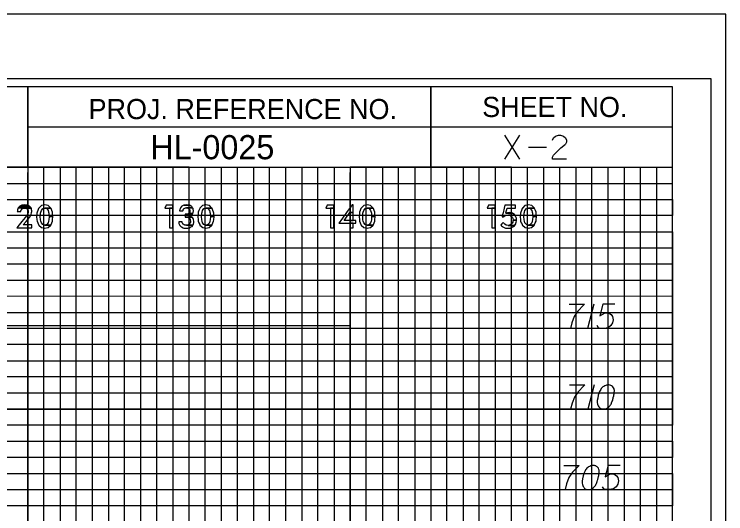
# Model space of a CAD drawing. Extents: x -13 to 323, y -5 to 1431.
# Drawn here: x 279.16 to 323.3, y 183.5 to 214.5 of the extents above; entities that cross this region are included whole.
import ezdxf

# ---------------------------------------------------------------- set-up
doc = ezdxf.new("R2010")
doc.units = 0
for name, color, linetype in [('Prop XS Elevation Labels', 7, 'Continuous'), ('Prop XS Offset Labels', 7, 'Continuous'), ('Prop XS Project Number', 7, 'Continuous'), ('Prop XS Sheet Number', 7, 'Continuous'), ('Scratch_Level_3', 7, 'Continuous'), ('Sheet Cross Section CELL', 7, 'Continuous'), ('Sheet Cross Section Grid Major CELL', 7, 'Continuous'), ('Sheet Cross Section Grid Middle CELL', 7, 'Continuous'), ('Sheet Cross Section Grid Minor 1 CELL', 7, 'Continuous'), ('Sheet Cross Section Grid Minor 2 CELL', 7, 'Continuous'), ('Sheet Cutting Line CELL', 7, 'Continuous'), ('Sheet DOT Grid CELL', 7, 'Continuous'), ('Sheet Plot Border Inside CELL', 7, 'Continuous'), ('Sheet Plot Border Outside CELL', 7, 'Continuous')]:
    doc.layers.add(name, color=color, linetype=linetype)

msp = doc.modelspace()

# ---------------------------------------------------------------- linework, layer by layer
at = {"layer": 'Prop XS Elevation Labels'}
for p, q in [((315.124, 196.5), (314.723, 195)), ((315.142, 191.5), (314.74, 190))]:
    msp.add_line(p, q, dxfattribs=at)
for points in [[(313.589, 196.5), (314.533, 196.5), (314.474, 196.441), (314.132, 196.075), (313.896, 195.744), (313.754, 195.354), (313.659, 195)], [(316.411, 196.5), (315.667, 196.5), (315.478, 195.791), (315.821, 195.969), (316.022, 195.969), (316.187, 195.862), (316.282, 195.744), (316.305, 195.543), (316.27, 195.342), (316.175, 195.177), (316.01, 195.047), (315.726, 195), (315.514, 195), (315.408, 195.047), (315.313, 195.177)], [(313.606, 191.5), (314.551, 191.5), (314.492, 191.441), (314.149, 191.075), (313.913, 190.744), (313.772, 190.354), (313.677, 190)], [(316.039, 191.5), (316.016, 191.5), (315.945, 191.488), (315.898, 191.476), (315.862, 191.465), (315.803, 191.441), (315.732, 191.406), (315.673, 191.37), (315.614, 191.323), (315.579, 191.276), (315.543, 191.217), (315.508, 191.158), (315.472, 191.087), (315.449, 191.039), (315.425, 190.969), (315.39, 190.85), (315.354, 190.673), (315.331, 190.531), (315.331, 190.402), (315.343, 190.307), (315.39, 190.201), (315.425, 190.142), (315.484, 190.071), (315.555, 190.024), (315.591, 190.012), (315.661, 190), (315.72, 190), (315.815, 190.012), (315.898, 190.035), (315.957, 190.071), (316.039, 190.13), (316.075, 190.165), (316.122, 190.213), (316.157, 190.26), (316.181, 190.295), (316.205, 190.354), (316.217, 190.378), (316.24, 190.437), (316.264, 190.508), (316.287, 190.579), (316.299, 190.626), (316.311, 190.661), (316.323, 190.709), (316.347, 190.815), (316.358, 190.874), (316.37, 190.933), (316.382, 191.016), (316.394, 191.122), (316.394, 191.158), (316.382, 191.205), (316.37, 191.252), (316.335, 191.323), (316.299, 191.37), (316.264, 191.406), (316.217, 191.441), (316.169, 191.465), (316.134, 191.476), (316.098, 191.488), (316.039, 191.5)], [(313.258, 186.5), (314.203, 186.5), (314.144, 186.441), (313.801, 186.075), (313.565, 185.744), (313.423, 185.354), (313.329, 185)], [(315.1, 186.5), (315.077, 186.5), (315.006, 186.488), (314.959, 186.476), (314.923, 186.465), (314.864, 186.441), (314.793, 186.406), (314.734, 186.37), (314.675, 186.323), (314.64, 186.276), (314.604, 186.217), (314.569, 186.158), (314.534, 186.087), (314.51, 186.039), (314.486, 185.969), (314.451, 185.85), (314.415, 185.673), (314.392, 185.531), (314.392, 185.402), (314.404, 185.307), (314.451, 185.201), (314.486, 185.142), (314.545, 185.071), (314.616, 185.024), (314.652, 185.012), (314.723, 185), (314.781, 185), (314.876, 185.012), (314.959, 185.035), (315.018, 185.071), (315.1, 185.13), (315.136, 185.165), (315.183, 185.213), (315.219, 185.26), (315.242, 185.295), (315.266, 185.354), (315.278, 185.378), (315.301, 185.437), (315.325, 185.508), (315.349, 185.579), (315.36, 185.626), (315.372, 185.661), (315.384, 185.709), (315.408, 185.815), (315.419, 185.874), (315.431, 185.933), (315.443, 186.016), (315.455, 186.122), (315.455, 186.158), (315.443, 186.205), (315.431, 186.252), (315.396, 186.323), (315.36, 186.37), (315.325, 186.406), (315.278, 186.441), (315.23, 186.465), (315.195, 186.476), (315.16, 186.488), (315.1, 186.5)], [(316.742, 186.5), (315.998, 186.5), (315.809, 185.791), (316.152, 185.969), (316.352, 185.969), (316.518, 185.862), (316.612, 185.744), (316.636, 185.543), (316.6, 185.342), (316.506, 185.177), (316.341, 185.047), (316.057, 185), (315.845, 185), (315.738, 185.047), (315.644, 185.177)]]:
    msp.add_lwpolyline(points, dxfattribs=at)
at = {"layer": 'Prop XS Offset Labels'}
for points in [[(279.512, 202.585), (279.507, 202.583), (280.108, 202.583), (280.106, 202.585), (279.974, 202.645), (279.958, 202.652), (279.794, 202.668), (279.794, 202.668), (279.685, 202.652), (279.637, 202.645)], [(280.851, 201.255), (281.051, 201.214), (281.245, 201.255), (281.256, 201.257), (281.422, 201.409), (281.048, 201.409), (281.038, 201.411), (281.033, 201.413), (280.928, 201.442), (280.841, 201.555), (280.841, 201.556), (280.841, 201.556), (280.813, 201.657), (280.813, 201.659), (280.793, 201.732), (280.792, 201.736), (280.774, 201.939), (280.774, 201.941), (280.774, 201.943), (280.792, 202.145), (280.812, 202.222), (280.813, 202.224), (280.839, 202.322), (280.84, 202.325), (280.928, 202.44), (281.041, 202.469), (281.045, 202.47), (281.055, 202.473), (281.425, 202.473), (281.262, 202.622), (281.254, 202.624), (281.053, 202.668), (281.053, 202.668), (280.845, 202.624), (280.843, 202.622), (280.681, 202.473), (280.678, 202.47), (280.678, 202.469), (280.665, 202.44), (280.618, 202.325), (280.617, 202.322), (280.577, 202.224), (280.576, 202.222), (280.568, 202.145), (280.547, 201.943), (280.547, 201.941), (280.547, 201.939), (280.567, 201.736), (280.567, 201.732), (280.575, 201.659), (280.575, 201.657), (280.616, 201.556), (280.617, 201.555), (280.663, 201.442), (280.675, 201.413), (280.676, 201.411), (280.679, 201.409), (280.848, 201.257)], [(288.581, 202.641), (288.492, 202.459), (288.99, 202.459), (288.99, 202.641)], [(289.42, 202.315), (289.418, 202.297), (289.626, 202.297), (289.627, 202.315), (289.639, 202.365), (289.64, 202.372), (289.641, 202.373), (289.683, 202.433), (289.688, 202.436), (289.696, 202.44), (289.748, 202.47), (289.785, 202.476), (289.795, 202.478), (289.835, 202.485), (290.217, 202.485), (290.165, 202.561), (290.129, 202.582), (290.128, 202.582), (290.022, 202.644), (289.982, 202.65), (289.69, 202.65), (289.678, 202.644), (289.553, 202.582), (289.536, 202.561), (289.471, 202.485), (289.466, 202.478), (289.465, 202.476), (289.463, 202.47), (289.452, 202.44), (289.45, 202.436), (289.449, 202.433), (289.428, 202.373), (289.427, 202.372), (289.425, 202.365)], [(289.853, 202.668), (289.69, 202.65), (289.982, 202.65)], [(290.851, 201.255), (291.051, 201.214), (291.245, 201.255), (291.256, 201.257), (291.422, 201.409), (291.048, 201.409), (291.038, 201.411), (291.033, 201.413), (290.928, 201.442), (290.841, 201.555), (290.841, 201.556), (290.841, 201.556), (290.813, 201.657), (290.813, 201.659), (290.793, 201.732), (290.792, 201.736), (290.774, 201.939), (290.774, 201.941), (290.774, 201.943), (290.792, 202.145), (290.812, 202.222), (290.813, 202.224), (290.839, 202.322), (290.84, 202.325), (290.928, 202.44), (291.041, 202.469), (291.045, 202.47), (291.055, 202.473), (291.425, 202.473), (291.262, 202.622), (291.254, 202.624), (291.053, 202.668), (291.053, 202.668), (290.845, 202.624), (290.843, 202.622), (290.681, 202.473), (290.678, 202.47), (290.678, 202.469), (290.665, 202.44), (290.618, 202.325), (290.617, 202.322), (290.577, 202.224), (290.576, 202.222), (290.568, 202.145), (290.547, 201.943), (290.547, 201.941), (290.547, 201.939), (290.567, 201.736), (290.567, 201.732), (290.575, 201.659), (290.575, 201.657), (290.616, 201.556), (290.617, 201.555), (290.663, 201.442), (290.675, 201.413), (290.676, 201.411), (290.679, 201.409), (290.848, 201.257)], [(298.581, 202.641), (298.492, 202.459), (298.99, 202.459), (298.99, 202.641)], [(299.411, 201.693), (299.297, 201.534), (300.35, 201.534), (300.35, 201.693), (299.618, 201.693), (299.878, 202.059), (299.935, 202.139), (299.977, 202.199), (300.179, 202.199), (300.179, 202.668), (300.114, 202.668), (299.775, 202.199), (299.733, 202.139), (299.675, 202.059)], [(300.851, 201.255), (301.051, 201.214), (301.245, 201.255), (301.256, 201.257), (301.422, 201.409), (301.048, 201.409), (301.038, 201.411), (301.033, 201.413), (300.928, 201.442), (300.841, 201.555), (300.841, 201.556), (300.841, 201.556), (300.813, 201.657), (300.813, 201.659), (300.793, 201.732), (300.792, 201.736), (300.774, 201.939), (300.774, 201.941), (300.774, 201.943), (300.792, 202.145), (300.812, 202.222), (300.813, 202.224), (300.839, 202.322), (300.84, 202.325), (300.928, 202.44), (301.041, 202.469), (301.045, 202.47), (301.055, 202.473), (301.425, 202.473), (301.262, 202.622), (301.254, 202.624), (301.053, 202.668), (301.053, 202.668), (300.845, 202.624), (300.843, 202.622), (300.681, 202.473), (300.678, 202.47), (300.678, 202.469), (300.665, 202.44), (300.618, 202.325), (300.617, 202.322), (300.577, 202.224), (300.576, 202.222), (300.568, 202.145), (300.547, 201.943), (300.547, 201.941), (300.547, 201.939), (300.567, 201.736), (300.567, 201.732), (300.575, 201.659), (300.575, 201.657), (300.616, 201.556), (300.617, 201.555), (300.663, 201.442), (300.675, 201.413), (300.676, 201.411), (300.679, 201.409), (300.848, 201.257)], [(308.581, 202.641), (308.492, 202.459), (308.99, 202.459), (308.99, 202.641)], [(309.427, 201.94), (309.424, 201.928), (309.495, 201.928), (309.508, 201.94), (309.524, 201.954), (309.595, 201.997), (309.627, 202.007), (309.697, 202.029), (309.811, 202.035), (310.219, 202.035), (310.211, 202.05), (310.076, 202.145), (309.655, 202.145), (309.658, 202.158), (309.658, 202.158), (309.663, 202.178), (309.738, 202.456), (310.263, 202.456), (310.263, 202.641), (309.6, 202.641), (309.554, 202.456), (309.486, 202.178), (309.481, 202.158), (309.478, 202.145), (309.454, 202.05), (309.451, 202.035), (309.449, 202.029), (309.444, 202.007), (309.441, 201.997), (309.431, 201.954)], [(310.851, 201.255), (311.051, 201.214), (311.245, 201.255), (311.256, 201.257), (311.422, 201.409), (311.048, 201.409), (311.038, 201.411), (311.033, 201.413), (310.928, 201.442), (310.841, 201.555), (310.841, 201.556), (310.841, 201.556), (310.813, 201.657), (310.813, 201.659), (310.793, 201.732), (310.792, 201.736), (310.774, 201.939), (310.774, 201.941), (310.774, 201.943), (310.792, 202.145), (310.812, 202.222), (310.813, 202.224), (310.839, 202.322), (310.84, 202.325), (310.928, 202.44), (311.041, 202.469), (311.045, 202.47), (311.055, 202.473), (311.425, 202.473), (311.262, 202.622), (311.254, 202.624), (311.053, 202.668), (311.053, 202.668), (310.845, 202.624), (310.843, 202.622), (310.681, 202.473), (310.678, 202.47), (310.678, 202.469), (310.665, 202.44), (310.618, 202.325), (310.617, 202.322), (310.577, 202.224), (310.576, 202.222), (310.568, 202.145), (310.547, 201.943), (310.547, 201.941), (310.547, 201.939), (310.567, 201.736), (310.567, 201.732), (310.575, 201.659), (310.575, 201.657), (310.616, 201.556), (310.617, 201.555), (310.663, 201.442), (310.675, 201.413), (310.676, 201.411), (310.679, 201.409), (310.848, 201.257)], [(279.465, 201.432), (279.313, 201.25), (280.253, 201.25), (280.253, 201.432), (279.719, 201.432), (279.898, 201.638), (280.095, 201.879), (280.097, 201.881), (280.208, 202.069), (280.208, 202.069), (280.211, 202.074), (280.235, 202.193), (280.247, 202.254), (280.252, 202.279), (280.25, 202.29), (280.249, 202.293), (280.236, 202.354), (280.235, 202.36), (280.233, 202.37), (280.222, 202.421), (280.222, 202.421), (280.219, 202.435), (280.213, 202.461), (280.211, 202.464), (280.207, 202.468), (279.839, 202.468), (279.85, 202.464), (279.858, 202.461), (279.933, 202.435), (279.946, 202.421), (279.996, 202.37), (280, 202.36), (280.002, 202.354), (280.022, 202.293), (280.022, 202.29), (280.022, 202.279), (280.022, 202.254), (280.021, 202.193), (279.973, 202.074), (279.972, 202.069), (279.839, 201.881), (279.838, 201.879), (279.637, 201.638)], [(279.349, 202.279), (279.347, 202.254), (279.567, 202.254), (279.569, 202.279), (279.57, 202.29), (279.571, 202.293), (279.593, 202.354), (279.598, 202.36), (279.606, 202.37), (279.645, 202.421), (279.673, 202.435), (279.725, 202.461), (279.73, 202.464), (279.839, 202.468), (280.207, 202.468), (280.197, 202.479), (279.41, 202.479), (279.405, 202.468), (279.403, 202.464), (279.402, 202.461), (279.39, 202.435), (279.384, 202.421), (279.361, 202.37), (279.357, 202.36), (279.356, 202.354), (279.35, 202.293), (279.35, 202.29)], [(279.507, 202.583), (279.41, 202.479), (280.197, 202.479), (280.108, 202.583)], [(281.312, 202.145), (281.328, 201.943), (281.555, 201.943), (281.536, 202.145), (281.528, 202.222), (281.528, 202.224), (281.527, 202.224), (281.488, 202.322), (281.488, 202.322), (281.487, 202.325), (281.441, 202.44), (281.44, 202.44), (281.429, 202.469), (281.428, 202.47), (281.425, 202.473), (281.055, 202.473), (281.065, 202.47), (281.068, 202.469), (281.175, 202.44), (281.262, 202.325), (281.265, 202.322), (281.291, 202.224), (281.291, 202.222)], [(288.781, 202.459), (288.781, 201.25), (288.99, 201.25), (288.99, 202.459)], [(290.007, 202.155), (289.988, 202.131), (290.23, 202.131), (290.246, 202.155), (290.254, 202.201), (290.271, 202.289), (290.272, 202.295), (290.272, 202.297), (290.269, 202.315), (290.26, 202.365), (290.259, 202.372), (290.259, 202.373), (290.259, 202.373), (290.249, 202.433), (290.248, 202.436), (290.248, 202.44), (290.227, 202.47), (290.223, 202.476), (290.222, 202.478), (290.217, 202.485), (289.835, 202.485), (289.901, 202.478), (289.919, 202.476), (289.931, 202.47), (289.986, 202.44), (289.995, 202.436), (289.997, 202.433), (290.04, 202.373), (290.04, 202.372), (290.042, 202.365), (290.051, 202.315), (290.054, 202.297), (290.055, 202.295), (290.056, 202.289), (290.041, 202.201)], [(291.312, 202.145), (291.328, 201.943), (291.555, 201.943), (291.536, 202.145), (291.528, 202.222), (291.528, 202.224), (291.527, 202.224), (291.488, 202.322), (291.488, 202.322), (291.487, 202.325), (291.441, 202.44), (291.44, 202.44), (291.429, 202.469), (291.428, 202.47), (291.425, 202.473), (291.055, 202.473), (291.065, 202.47), (291.068, 202.469), (291.175, 202.44), (291.262, 202.325), (291.265, 202.322), (291.291, 202.224), (291.291, 202.222)], [(298.781, 202.459), (298.781, 201.25), (298.99, 201.25), (298.99, 202.459)], [(299.97, 202.059), (299.97, 201.693), (300.179, 201.693), (300.179, 202.059), (300.179, 202.139), (300.179, 202.199), (299.977, 202.199), (299.973, 202.139)], [(301.312, 202.145), (301.328, 201.943), (301.555, 201.943), (301.536, 202.145), (301.528, 202.222), (301.528, 202.224), (301.527, 202.224), (301.488, 202.322), (301.488, 202.322), (301.487, 202.325), (301.441, 202.44), (301.44, 202.44), (301.429, 202.469), (301.428, 202.47), (301.425, 202.473), (301.055, 202.473), (301.065, 202.47), (301.068, 202.469), (301.175, 202.44), (301.262, 202.325), (301.265, 202.322), (301.291, 202.224), (301.291, 202.222)], [(308.781, 202.459), (308.781, 201.25), (308.99, 201.25), (308.99, 202.459)], [(309.692, 202.158), (309.655, 202.145), (310.076, 202.145), (310.058, 202.158), (309.961, 202.178), (309.75, 202.178)], [(309.888, 202.192), (309.75, 202.178), (309.96, 202.178), (309.888, 202.192)], [(311.312, 202.145), (311.328, 201.943), (311.555, 201.943), (311.536, 202.145), (311.528, 202.222), (311.528, 202.224), (311.527, 202.224), (311.488, 202.322), (311.488, 202.322), (311.487, 202.325), (311.441, 202.44), (311.44, 202.44), (311.429, 202.469), (311.428, 202.47), (311.425, 202.473), (311.055, 202.473), (311.065, 202.47), (311.068, 202.469), (311.175, 202.44), (311.262, 202.325), (311.265, 202.322), (311.291, 202.224), (311.291, 202.222)], [(281.058, 201.411), (281.048, 201.409), (281.422, 201.409), (281.425, 201.411), (281.426, 201.413), (281.438, 201.442), (281.485, 201.555), (281.485, 201.556), (281.527, 201.657), (281.528, 201.659), (281.535, 201.732), (281.535, 201.736), (281.555, 201.939), (281.556, 201.941), (281.555, 201.943), (281.328, 201.943), (281.328, 201.941), (281.328, 201.939), (281.312, 201.736), (281.312, 201.732), (281.292, 201.659), (281.291, 201.657), (281.264, 201.556), (281.263, 201.555), (281.175, 201.442), (281.063, 201.413)], [(289.765, 201.956), (289.765, 201.9), (290.194, 201.9), (290.119, 201.956), (290.029, 201.983), (290.095, 202), (290.181, 202.053), (290.2, 202.084), (290.201, 202.085), (290.207, 202.095), (289.915, 202.095), (289.83, 202.085), (289.765, 202.084), (289.765, 202.053), (289.765, 202), (289.765, 201.983)], [(289.925, 201.416), (289.849, 201.401), (290.229, 201.401), (290.239, 201.416), (290.243, 201.423), (290.243, 201.423), (290.275, 201.471), (290.277, 201.479), (290.277, 201.482), (290.283, 201.516), (290.292, 201.562), (290.293, 201.567), (290.303, 201.62), (290.297, 201.662), (290.285, 201.751), (290.283, 201.763), (290.25, 201.826), (290.223, 201.877), (290.222, 201.88), (290.197, 201.898), (290.194, 201.9), (289.81, 201.9), (289.877, 201.898), (289.951, 201.88), (289.963, 201.877), (290.033, 201.826), (290.07, 201.763), (290.077, 201.751), (290.092, 201.662), (290.088, 201.62), (290.082, 201.567), (290.08, 201.562), (290.057, 201.516), (290.039, 201.482), (290.035, 201.479), (290.025, 201.471), (289.957, 201.423)], [(289.988, 202.131), (289.915, 202.095), (290.207, 202.095), (290.23, 202.131)], [(291.058, 201.411), (291.048, 201.409), (291.422, 201.409), (291.425, 201.411), (291.426, 201.413), (291.438, 201.442), (291.485, 201.555), (291.485, 201.556), (291.527, 201.657), (291.528, 201.659), (291.535, 201.732), (291.535, 201.736), (291.555, 201.939), (291.556, 201.941), (291.555, 201.943), (291.328, 201.943), (291.328, 201.941), (291.328, 201.939), (291.312, 201.736), (291.312, 201.732), (291.292, 201.659), (291.291, 201.657), (291.264, 201.556), (291.263, 201.555), (291.175, 201.442), (291.063, 201.413)], [(301.058, 201.411), (301.048, 201.409), (301.422, 201.409), (301.425, 201.411), (301.426, 201.413), (301.438, 201.442), (301.485, 201.555), (301.485, 201.556), (301.527, 201.657), (301.528, 201.659), (301.535, 201.732), (301.535, 201.736), (301.555, 201.939), (301.556, 201.941), (301.555, 201.943), (301.328, 201.943), (301.328, 201.941), (301.328, 201.939), (301.312, 201.736), (301.312, 201.732), (301.292, 201.659), (301.291, 201.657), (301.264, 201.556), (301.263, 201.555), (301.175, 201.442), (301.063, 201.413)], [(309.424, 201.928), (309.482, 201.916), (309.495, 201.928)], [(310.083, 201.841), (310.105, 201.721), (310.318, 201.721), (310.307, 201.841), (310.307, 201.841), (310.303, 201.881), (310.284, 201.916), (310.278, 201.928), (310.271, 201.94), (310.263, 201.954), (310.24, 201.997), (310.235, 202.007), (310.223, 202.029), (310.219, 202.035), (309.811, 202.035), (309.838, 202.029), (309.928, 202.007), (309.942, 201.997), (310.003, 201.954), (310.024, 201.94), (310.031, 201.928), (310.038, 201.916), (310.059, 201.881)], [(311.058, 201.411), (311.048, 201.409), (311.422, 201.409), (311.425, 201.411), (311.426, 201.413), (311.438, 201.442), (311.485, 201.555), (311.485, 201.556), (311.527, 201.657), (311.528, 201.659), (311.535, 201.732), (311.535, 201.736), (311.555, 201.939), (311.556, 201.941), (311.555, 201.943), (311.328, 201.943), (311.328, 201.941), (311.328, 201.939), (311.312, 201.736), (311.312, 201.732), (311.292, 201.659), (311.291, 201.657), (311.264, 201.556), (311.263, 201.555), (311.175, 201.442), (311.063, 201.413)], [(289.677, 201.229), (289.854, 201.214), (289.936, 201.229), (290.042, 201.248), (290.123, 201.297), (290.187, 201.336), (290.228, 201.399), (290.229, 201.401), (289.849, 201.401), (289.72, 201.416), (289.711, 201.423), (289.639, 201.471), (289.628, 201.479), (289.626, 201.482), (289.608, 201.516), (289.584, 201.562), (289.584, 201.567), (289.58, 201.62), (289.58, 201.625), (289.361, 201.625), (289.362, 201.62), (289.369, 201.567), (289.37, 201.562), (289.377, 201.516), (289.391, 201.482), (289.392, 201.479), (289.395, 201.471), (289.415, 201.423), (289.418, 201.416), (289.425, 201.401), (289.426, 201.399), (289.49, 201.336), (289.53, 201.297), (289.635, 201.248)], [(299.97, 201.534), (299.97, 201.25), (300.179, 201.25), (300.179, 201.534)], [(309.626, 201.233), (309.762, 201.214), (309.959, 201.233), (309.968, 201.237), (310.091, 201.297), (310.091, 201.297), (310.141, 201.321), (310.185, 201.375), (310.204, 201.399), (309.793, 201.399), (309.683, 201.418), (309.682, 201.419), (309.679, 201.42), (309.596, 201.466), (309.586, 201.477), (309.58, 201.483), (309.58, 201.483), (309.529, 201.535), (309.497, 201.585), (309.497, 201.585), (309.451, 201.535), (309.404, 201.483), (309.399, 201.477), (309.39, 201.466), (309.348, 201.42), (309.347, 201.419), (309.348, 201.418), (309.363, 201.399), (309.382, 201.375), (309.445, 201.321), (309.474, 201.297), (309.598, 201.237)], [(309.9, 201.418), (309.793, 201.399), (310.204, 201.399), (310.22, 201.418), (310.221, 201.419), (310.222, 201.42), (310.222, 201.42), (310.259, 201.466), (310.268, 201.477), (310.27, 201.483), (310.284, 201.535), (310.299, 201.59), (310.322, 201.674), (310.318, 201.721), (310.105, 201.721), (310.097, 201.674), (310.082, 201.59), (310.047, 201.535), (310.014, 201.483), (310.004, 201.477), (309.987, 201.466), (309.913, 201.42), (309.905, 201.419)]]:
    msp.add_lwpolyline(points, close=True, dxfattribs=at)
at = {"layer": 'Prop XS Sheet Number'}
for p, q in [((309.575, 207), (310.508, 205.5)), ((310.508, 207), (309.575, 205.5)), ((311.063, 206.256), (312.185, 206.256))]:
    msp.add_line(p, q, dxfattribs=at)
for points in [[(312.551, 206.693), (312.61, 206.823), (312.74, 206.941), (312.929, 207), (313.047, 207), (313.236, 206.941), (313.366, 206.823), (313.425, 206.693), (313.425, 206.563), (313.366, 206.445)], [(313.425, 205.5), (312.551, 205.5), (312.551, 205.63), (312.61, 205.748), (313.071, 206.209), (313.366, 206.445)]]:
    msp.add_lwpolyline(points, dxfattribs=at)
at = {"layer": 'Scratch_Level_3'}
msp.add_lwpolyline([(20, 195.176), (300, 195.176), (300, 165.176), (20, 165.176)], close=True, dxfattribs=at)
at = {"layer": 'Sheet Cross Section CELL'}
for p, q in [((305, 210), (305, 205)), ((305, 205), (305, 210)), ((280, 207.5), (280, 205)), ((320, 207.49), (280, 207.49)), ((280, 205), (320, 205))]:
    msp.add_line(p, q, dxfattribs=at)
for points in [[(320, 210), (0, 210), (0, 0), (320, 0)], [(280, 210), (260, 210), (260, 205.03), (280, 205.03)], [(320, 210), (280, 210), (280, 205), (320, 205)]]:
    msp.add_lwpolyline(points, close=True, dxfattribs=at)
at = {"layer": 'Sheet Cross Section Grid Major CELL'}
for p, q in [((290, 205), (280, 205)), ((280, 205), (280, 0)), ((290, 0), (290, 205)), ((310, 205), (300, 205)), ((300, 205), (300, 0)), ((310, 0), (310, 205))]:
    msp.add_line(p, q, dxfattribs=at)
msp.add_lwpolyline([(0, 200), (320, 200), (320, 190), (0, 190)], dxfattribs=at)
at = {"layer": 'Sheet Cross Section Grid Middle CELL'}
for points in [[(275, 0), (275, 205), (285, 205), (285, 0)], [(295, 0), (295, 205), (305, 205), (305, 0)], [(315, 0), (315, 205)], [(0, 185), (320, 185), (320, 195), (0, 195)]]:
    msp.add_lwpolyline(points, dxfattribs=at)
at = {"layer": 'Sheet Cross Section Grid Minor 1 CELL'}
msp.add_line((0, 204), (320, 204), dxfattribs=at)
for points in [[(0, 203), (270, 203), (320, 203), (320, 202), (0, 202)], [(0, 201), (320, 201), (320, 199), (0, 199)], [(0, 198), (320, 198), (320, 197), (0, 196.98)], [(0, 196), (320, 196), (320, 194), (0, 194)], [(0, 193), (320, 193), (320, 192), (0, 192)], [(0, 191), (320, 191), (320, 189), (0, 189)], [(0, 188), (320, 188), (320, 187), (0, 187)], [(0, 186), (320, 186), (320, 184), (0, 184)]]:
    msp.add_lwpolyline(points, dxfattribs=at)
at = {"layer": 'Sheet Cross Section Grid Minor 2 CELL'}
for points in [[(280, 0), (281, 0), (281, 205), (282, 205), (282, 0)], [(282, 0), (283, 0), (283, 205), (284, 205), (284, 0)], [(285, 0), (286, 0), (286, 205), (287, 205), (287, 0)], [(287, 0), (288, 0), (288, 205), (289, 205), (289, 0)], [(290, 0), (291, 0), (291, 205), (292, 205), (292, 0)], [(292, 0), (293, 0), (293, 205), (294, 205), (294, 0)], [(295, 0), (296, 0), (296, 205), (297, 205), (297, 0)], [(297, 0), (298, 0), (298, 205), (299, 205), (299, 0)], [(300, 0), (301, 0), (301, 205), (302, 205), (302, 0)], [(302, 0), (303, 0), (303, 205), (304, 205), (304, 0)], [(305, 0), (306, 0), (306, 205), (307, 205), (307, 0)], [(307, 0), (308, 0), (308, 205), (309, 205), (309, 0)], [(310, 0), (311, 0), (311, 205), (312, 205), (312, 0)], [(312, 0), (313, 0), (313, 205), (314, 205), (314, 0)], [(315, 0), (316, 0), (316, 205), (317, 205), (317, 0)], [(317, 0), (318, 0), (318, 205), (319, 205), (319, 0)]]:
    msp.add_lwpolyline(points, dxfattribs=at)
at = {"layer": 'Sheet Cutting Line CELL'}
msp.add_line((323.3, 214.5), (-13.4, 214.5), dxfattribs=at)
at = {"layer": 'Sheet DOT Grid CELL'}
for p, q in [((280, 0), (280, 204.687)), ((290, 0), (290, 204.687)), ((300, 0), (300, 204.687)), ((310, 0), (310, 204.687)), ((0, 200), (320, 200)), ((0, 190), (320, 190))]:
    msp.add_line(p, q, dxfattribs=at)
at = {"layer": 'Sheet Plot Border Inside CELL'}
msp.add_lwpolyline([(-10.8, -0.5), (322.4, -0.5), (322.4, 210.5), (-10.8, 210.5)], close=True, dxfattribs=at)
at = {"layer": 'Sheet Plot Border Outside CELL'}
msp.add_lwpolyline([(-13.4, -4.5), (323.3, -4.5), (323.3, 214.5), (-13.4, 214.5)], close=True, dxfattribs=at)

# ---------------------------------------------------------------- texts
at = {"layer": 'Prop XS Project Number'}
msp.add_text('HL-0025', height=1.5, dxfattribs=at).set_placement((287.598, 205.5))
at = {"layer": 'Sheet Cross Section CELL'}
for s, height, p in [('PROJ. REFERENCE NO.', 1.24998, (283.77, 207.99)), ('SHEET NO.', 1.25, (308.19, 208.12))]:
    msp.add_text(s, height=height, dxfattribs=at).set_placement(p)

doc.saveas('drawing.dxf')
